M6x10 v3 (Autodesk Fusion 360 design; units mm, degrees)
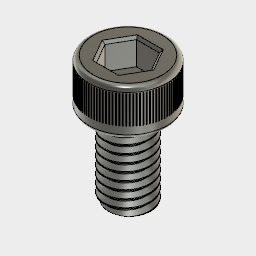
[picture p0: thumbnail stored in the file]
sketch "スケッチ1"
  circle C1 centre (0, 0) radius 3
  circle C2 centre (0, 0) radius 5
  dimension "d1" diameter C1 = 6
  dimension "d2" diameter C2 = 10
extrude "押し出し1" new body sketch "スケッチ1" blind 5.8
sketch "スケッチ2" plane through (0, 0, 5.8) normal (0, 0, 1) x axis (-1, 0, 0)
  line L1 (-1.4722, -2.55) -> (-2.9445, 0)
  line L2 (1.4722, -2.55) -> (-1.4722, -2.55)
  line L3 (2.9445, 0) -> (1.4722, -2.55)
  line L4 (1.4722, 2.55) -> (2.9445, 0)
  line L5 (-1.4722, 2.55) -> (1.4722, 2.55)
  line L6 (-2.9445, 0) -> (-1.4722, 2.55)
  circle C1 centre (0, 0) radius 5
  dimension "d5" distance L2 L5 = 5.1
work_plane "作業平面" sketch "スケッチ2" AlongDistance -0.75
extrude "押し出し2" cut sketch "スケッチ2" profile of L1 L2 L3 L4 L5 L6 against normal blind 3.3
chamfer "面取り" distance 0.3
sketch "スケッチ3" plane through (0, 0, 5.05) normal (0, 0, 1) x axis (1, 0, 0)
  line L1 (-0.05, 4.9497) -> (-0.05, 4.9997)
  line L2 (0.05, 4.9497) -> (-0.05, 4.9497)
  line L3 (0.05, 4.9997) -> (0.05, 4.9497)
  circle C1 centre (0, 0) radius 5
  point P4 (-0.05, 4.9497)
  point P5 (0.05, 4.9497)
  point P3 (-0.05, 4.9997)
  point P6 (0.05, 4.9997)
  dimension "d18" distance P4 P5 = 0.1
  dimension "d19" distance P3 P4 = 0.05
  dimension "d20" distance P5 P6 = 0.05 (= "d19")
extrude "押し出し3" cut sketch "スケッチ3" against normal blind 3.6
work_axis "作業軸"
circular_pattern "C パターン" countU 100 TotalAngle 360
fillet "フィレット1" radius 0.6
extrude "押し出し4" sketch "スケッチ1" profile of C1 blind -10
thread "ねじ"
fillet "フィレット2" sketch "スケッチ3" radius 0.5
